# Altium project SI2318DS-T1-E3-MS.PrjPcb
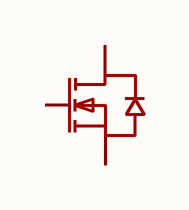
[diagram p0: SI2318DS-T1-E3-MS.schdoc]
1 sheet, 1 parts. Net scope: global (net labels, ports and power ports of the same name join across sheets).

## Sheet SI2318DS-T1-E3-MS.schdoc
size 127 x 101 mm

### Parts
Q?  si2318ds-t1-e3-ms  [SOT-23-3_L2.9-W1.3-P1.90-LS2.4-BR]  (value not drawn)

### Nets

Not connected (* = marked no-connect by the designer): Q? 1(G) 2(S) 3(D)

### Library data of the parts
Q? = si2318ds-t1-e3-ms: 数量:1个N沟道;漏源电压(Vdss):40V;连续漏极电流(Id):4A;导通电阻(RDS(on)):36mΩ@10V；45mΩ@4.5V;耗散功率(Pd):1.56W;阈值电压(Vgs(th)):1.6V;; Manufacturer: MSKSEMI(美森科); AddInBom: yes; ModelId: c62791f0466c4ae2a892c056b845b0ca; ModelName: SOT-23-3P_L2.9-W1.3-H1.0-LS2.4-P0.95; ModelTransform: 98.425,114.173,0,180,0,0,0.0005,-0.0005,0; Number: 1个N沟道; Drain to Source Voltage: 40V; Current - Continuous Drain(Id): 4A; Pd - Power Dissipation: 1.56W; Gate Threshold Voltage (Vgs(th)): 1.6V; Gate Charge(Qg): 4.7nC@4.5V; Input Capacitance(Ciss): 420pF; Reverse Transfer Capacitance (Crss@Vds): 40pF; Type: N沟道; Output Capacitance(Coss): 65pF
